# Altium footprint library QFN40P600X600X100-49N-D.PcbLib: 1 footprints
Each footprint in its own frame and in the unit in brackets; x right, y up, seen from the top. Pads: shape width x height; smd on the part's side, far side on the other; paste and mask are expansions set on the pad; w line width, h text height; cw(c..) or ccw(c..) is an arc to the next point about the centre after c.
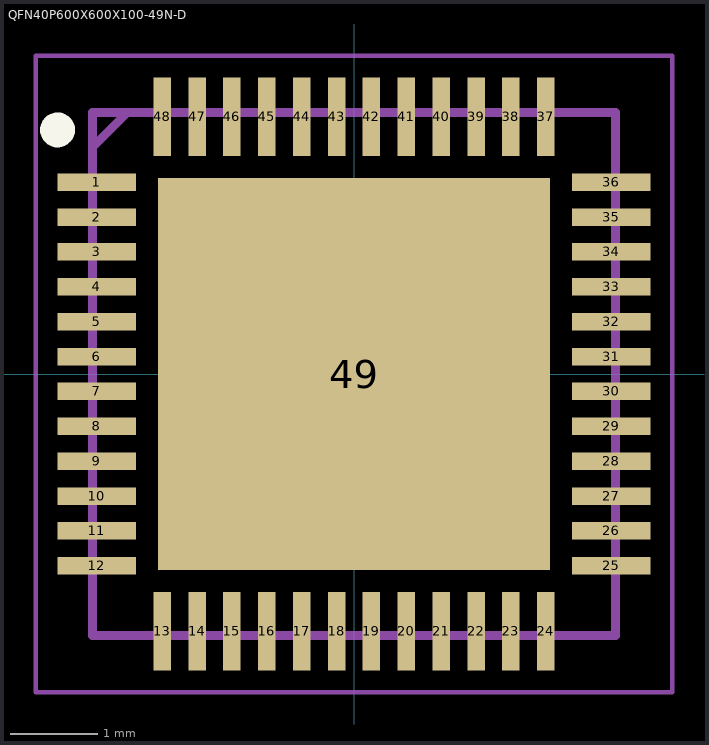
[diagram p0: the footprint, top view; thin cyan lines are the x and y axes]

## QFN40P600X600X100-49N-D [mm]
pads (49):
  rect 0.9x0.2 smd: 1(-2.95,2.2) 2(-2.95,1.8) 3(-2.95,1.4) 4(-2.95,1) 5(-2.95,0.6) 6(-2.95,0.2) 7(-2.95,-0.2) 8(-2.95,-0.6) 9(-2.95,-1) 10(-2.95,-1.4) 11(-2.95,-1.8) 12(-2.95,-2.2) 25(2.95,-2.2) 26(2.95,-1.8) 27(2.95,-1.4) 28(2.95,-1) 29(2.95,-0.6) 30(2.95,-0.2) 31(2.95,0.2) 32(2.95,0.6) 33(2.95,1) 34(2.95,1.4) 35(2.95,1.8) 36(2.95,2.2)
  rect 0.2x0.9 smd: 13(-2.2,-2.95) 14(-1.8,-2.95) 15(-1.4,-2.95) 16(-1,-2.95) 17(-0.6,-2.95) 18(-0.2,-2.95) 19(0.2,-2.95) 20(0.6,-2.95) 21(1,-2.95) 22(1.4,-2.95) 23(1.8,-2.95) 24(2.2,-2.95) 37(2.2,2.95) 38(1.8,2.95) 39(1.4,2.95) 40(1,2.95) 41(0.6,2.95) 42(0.2,2.95) 43(-0.2,2.95) 44(-0.6,2.95) 45(-1,2.95) 46(-1.4,2.95) 47(-1.8,2.95) 48(-2.2,2.95)
  rect 4.5x4.5 smd: 49(0,0)
Top Overlay:
  circle w0.2: c-3.4,2.8 r0.1
Mechanical 15:
  lines w0.1: -3,2.6 -2.6,3 ; -3,-3 3,-3 3,3 -3,3 -3,-3
Mechanical 20:
  lines w0.05: -3.65,-3.65 3.65,-3.65 3.65,3.65 -3.65,3.65 -3.65,-3.65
